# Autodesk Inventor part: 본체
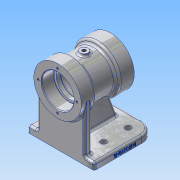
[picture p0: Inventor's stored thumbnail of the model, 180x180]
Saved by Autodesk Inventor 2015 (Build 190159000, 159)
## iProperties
Created: 2020-06
Part Number: 본체
Material: 알루미늄 6061
Document SubType Name: Modeling
Designer: user
Density: 2.7 g/cm^3
Appearance: 알루미늄 - 평지
Mass: 725.418 g
Surface Area: 641.499 cm^2
Volume: 268.673 cm^3
Author: user
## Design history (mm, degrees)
sketch "스케치1"
  geometry: L1 (0, 49)-(90, 49); L2 (90, 49)-(90, -49); L3 (90, -49)-(0, -49); L4 (0, -49)-(0, 49); 2 further points
  constraints: 8 end point, 2 parallel, 1 coincident, 1 horizontal, 1 midpoint, 1 perpendicular
  dimensions: "d0" = 90 distance of L1.start L1.end; "d1" = 98 distance of L1.end L2.end
extrude "돌출1" new body sketch "스케치1" distance "d2" = 10; taper "d3" = 0 deg
sketch "스케치2"
  geometry: L1 (0, 0)-(-90, 0) reference; L2 (5, 80)-(-73, 80); L3 (0, 0)-(0, 10) reference; L4 (5, 80)-(-17, 80); L5 (-17, 80)-(-17, 115); L6 (-17, 115)-(5, 115); L7 (5, 115)-(5, 80); L8 (-73, 80)-(-51, 80); L9 (-51, 80)-(-51, 115); L10 (-51, 115)-(-73, 115); L11 (-73, 115)-(-73, 80); L12 (-17, 80)-(-51, 80); L13 (-51, 80)-(-51, 109); L14 (-51, 109)-(-17, 109); L15 (-17, 109)-(-17, 80); 1 further point
  constraints: 26 end point, 6 parallel, 4 horizontal, 3 perpendicular, 1 collinear, 1 midpoint
  dimensions: "d7" = 80 distance between parallel lines of L1 L2; "d8" = 78 distance of L2.start L2.end; "d9" = 5 distance from line of L3 L2.start; "d10" = 22 distance of L5.end L6.end; "d11" = 35 distance of L6.end L2.start; "d12" = 22 distance of L9.end L10.end; "d13" = 35 distance of L10.end L2.end; "d14" = 29 distance between parallel lines of L12 L14
revolve "회전1" sketch "스케치2" stored, may be unused: angle "d15" = 90 deg
sketch "스케치3"
  geometry: L1 (0, 49)-(0, -49) reference; L2 (90, -49)-(90, 49) reference; L3 (0, 35)-(10, 35); L4 (10, 35)-(10, -35); L5 (10, -35)-(0, -35); L6 (0, -35)-(0, 35); L7 (0, 5)-(78, 5); L8 (78, 5)-(78, -5); L9 (78, -5)-(0, -5); L10 (0, -5)-(0, 5); 2 further points
  constraints: 16 end point, 4 parallel, 3 midpoint, 2 horizontal, 2 perpendicular
  dimensions: "d16" = 70 distance of L3.end L4.end; "d17" = 10 distance of L3.start L3.end; "d18" = 10 distance of L7.end L8.end; "d19" = 12 distance between parallel lines of L2 L8
extrude "돌출2" join sketch "스케치3" stored distance "d20" = 70; taper "d21" = 0 deg
sketch "스케치4"
  geometry: L1 (90, -49)-(90, 49) reference; L2 (0, 5)-(78, 5); L3 (78, 5)-(78, -5); L4 (78, -5)-(0, -5); L5 (0, -5)-(0, 5); 2 further points
  constraints: 8 end point, 2 parallel, 1 coincident, 1 horizontal, 1 midpoint, 1 perpendicular
  dimensions: "d22" = 10 distance of L2.end L3.end; "d23" = 12 distance between parallel lines of L1 L3
extrude "돌출3" join sketch "스케치4" distance "d24" = 70; taper "d25" = 0 deg
feature "면 기울기1" dims angle "d26" = 20 deg
sketch "스케치5"
  geometry: L1 (5, 80)-(-73, 80); L2 (5, 45)-(5, 115) reference; L3 (-73, 45)-(-73, 115) reference; L4 (0, 0)-(-90, 0) reference; L5 (5, 80)-(-13, 80); L6 (-13, 80)-(-13, 103.2); L7 (-12.7, 103.5)-(5, 103.5); L8 (5, 103.5)-(5, 80); L9 (-73, 80)-(-55, 80); L10 (-55, 80)-(-55, 103.2); L11 (-55.3, 103.5)-(-73, 103.5); L12 (-73, 103.5)-(-73, 80); L13 (-13, 80)-(-19, 80); L14 (-19, 80)-(-19, 100); L15 (-19, 100)-(-13, 100); L16 (-13, 100)-(-13, 80); L17 (-19, 80)-(-49, 80); L18 (-49, 80)-(-49, 100); L19 (-46, 103)-(-22, 103); L20 (-19, 100)-(-19, 80); L21 (-49, 80)-(-55, 80); L22 (-55, 80)-(-55, 100); L23 (-55, 100)-(-49, 100); L24 (-49, 100)-(-49, 80); A1 r 0.3 centre (-12.7, 103.2) between (-12.7, 103.5) and (-13, 103.2); A2 r 0.3 centre (-55.3, 103.2) between (-55, 103.2) and (-55.3, 103.5); A3 r 3 centre (-22, 100) between (-19, 100) and (-22, 103); A4 r 3 centre (-46, 100) between (-46, 103) and (-49, 100); 4 further points
  constraints: 42 end point, 10 parallel, 8 point on circle, 8 point on line, 8 tangent, 6 horizontal, 5 perpendicular, 4 centre point, 2 midpoint, 1 collinear, 1 equal radius
  dimensions: "d27" = 80 distance between parallel lines of L4 L1; "d28" = 18 distance of point (-13, 103.5) L7.end; "d29" = 23.5 distance between parallel lines of L1 L7; "d30" = 18 distance of point (-55, 103.5) L11.end; "d31" = 23.5 distance of L9.end point (-55, 103.5); "d32" = 6 distance of L14.end L15.end; "d33" = 20 distance of L13.end L14.end; "d34" = 23 distance of L17.end point (-49, 103); "d35" = 30 distance of point (-49, 103) point (-19, 103); "d36" = 20 distance of L9.end L22.end; "d37" = 0.3 radius of A1; "d38" = 0.3 radius of A2; "d39" = 3 radius of A3
revolve "회전2" sketch "스케치5" stored, may be unused: angle "d40" = 90 deg
fillet "모깎기1" dims "d41" = 3
fillet "모깎기2" dims "d42" = 3
fillet "모깎기3" dims "d43" = 20
fillet "모깎기4" dims "d44" = 3
fillet "모깎기5" dims "d45" = 3
fillet "모깎기6" dims "d46" = 3
fillet "모깎기7" dims "d47" = 3
fillet "모깎기8" dims "d48" = 3
fillet "모깎기9" dims "d49" = 3
chamfer "모따기1" distance "d50" = 1; stored, may be unused: second distance "d51" = 2, angle "d52" = 45 deg
node "작업 평면1"
sketch "스케치6"
  geometry: L1 (-5, 35)-(-5, -35) reference; L2 (87, 29)-(87, -29) reference; C1 r 6 at (34, 0); 2 further points
  constraints: 1 centre point, 1 horizontal alignment, 1 midpoint
  dimensions: "d54" = 39 distance from line of L1 C1.centre; "d55" = 12 diameter of C1
extrude "돌출4" join sketch "스케치6" stored distance "d56" = 70; taper "d57" = 0 deg
hole "구멍1" diameter "d60" = 5.188; stored, may be unused: countersink angle "d64" = 90 deg, drill point angle "d66" = 0 deg; dims "d58" = 10, "d59" = 10, "d61" = 16, "d62" = 4, "d63" = 2, "d65" = 20
sketch "스케치7"
  geometry: C1 r 35 at (0, 0) reference; 2 further points
  constraints: 1 horizontal alignment
  dimensions: "d67" = 28.5 distance of C1.centre point (28.5, 0)
hole "구멍2" sketch "스케치7" at (28.5, 0) diameter "d68" = 3.242; stored, may be unused: countersink angle "d72" = 90 deg, drill point angle "d74" = 118 deg; dims "d69" = 10, "d70" = 4, "d71" = 2, "d73" = 12
node "작업 평면2"
fillet "모깎기10" dims "d78" = 3
sketch "스케치8"
  geometry: L1 (0, 0)-(-67, 0) reference; L2 (-70, 7)-(-70, 0) reference; 1 further point
  constraints: 1 other
  dimensions: "d79" = 4 distance from line of L1 point (-25, 4); "d80" = 45 distance from line of point (-25, 4) L2
feature "엠보싱1" sketch "스케치8" dims "d0" = 90, "d1" = 98, "d7" = 80, "d8" = 78, "d9" = 5, "d10" = 22, "d11" = 35, "d12" = 22, "d13" = 35, "d14" = 29, "d81" = 0.5, "d82" = 0
sketch "스케치9"
  geometry: L1 (90, -29)-(90, 29) reference; L2 (70, 49)-(0, 49) reference; 3 further points
  dimensions: "d83" = 20 distance from line of L1 point (70, 29); "d84" = 20 distance from line of L2 point (70, 29); "d85" = 36 distance of point (70, 29) point (34, 29); "d86" = 20 distance from line of point (34, 29) L2
hole "구멍3" sketch "스케치9" at (70, 29), (34, 29) diameter "d87" = 9; stored, may be unused: countersink angle "d91" = 90 deg, drill point angle "d93" = 118 deg; dims "d88" = 10, "d89" = 4, "d90" = 2, "d92" = 12
fillet "모깎기11" dims "d94" = 3
node "솔리드1"
pattern_circular "원형 패턴1" dims angle "d76" = 360 deg
mirror "대칭1"
mirror "대칭2"
other parameters: "d53" = 112
